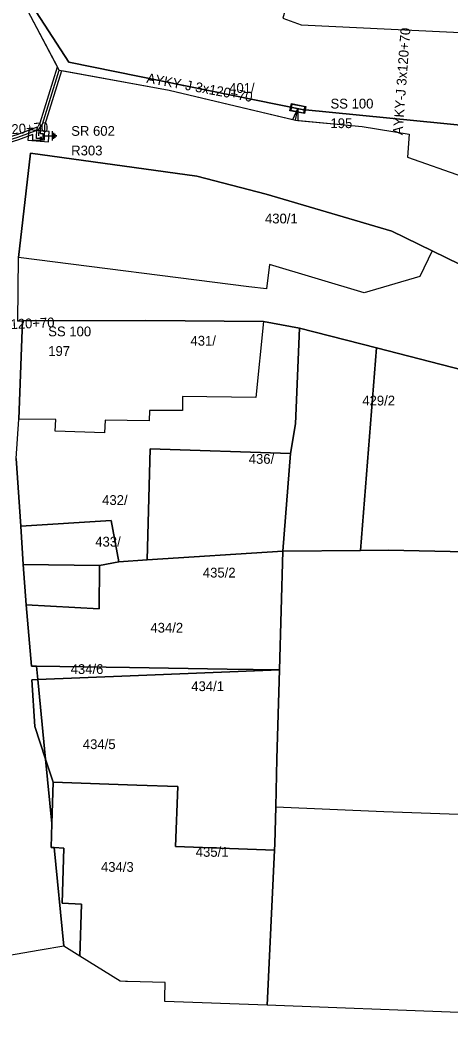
# Model space of a CAD drawing. Extents: x -793400 to -756198, y -1074141 to -1042963.
# Drawn here: x -783578.1 to -783545.2, y -1065386.8 to -1065310.2 of the extents above; entities that cross this region are included whole.
import ezdxf

# ---------------------------------------------------------------- set-up
doc = ezdxf.new("R2010")
doc.units = 0
for name, color, linetype in [('Parcela', 7, 'Continuous'), ('Popiskový text - Parcela', 7, 'Continuous'), ('Popiskový text - Přípojková skříň nn - SJZ', 7, 'Continuous'), ('Popiskový text - Přípojková skříň nn - Typ', 7, 'Continuous'), ('Popiskový text - Rozpojovací skříň nn - SJZ', 7, 'Continuous'), ('Popiskový text - Rozpojovací skříň nn - Typ', 7, 'Continuous'), ('Popiskový text - Vedení nn kabelové', 7, 'Continuous'), ('Skříň', 7, 'Continuous'), ('Spojnice nn', 7, 'Continuous'), ('Stavební objekt', 7, 'Continuous'), ('Uzemnění', 7, 'Continuous'), ('Vedení nn kabelové', 7, 'Continuous')]:
    doc.layers.add(name, color=color, linetype=linetype)

msp = doc.modelspace()

# ---------------------------------------------------------------- linework, layer by layer
at = {"layer": 'Parcela'}
for points in [[(-783571.78, -1065303.16), (-783560.13, -1065304.49), (-783552.66, -1065304.27), (-783552.7, -1065303.7), (-783552.39, -1065303.67), (-783546.16, -1065304.2), (-783541.16, -1065304.39), (-783541.22, -1065311.31), (-783541.24, -1065311.65), (-783541.28, -1065318.54), (-783556.53, -1065317.04), (-783574.41, -1065313.42), (-783576.91, -1065309.57), (-783575.57, -1065302.34)], [(-783542.31, -1065329.92), (-783544.32, -1065335.6), (-783540.78, -1065337.05), (-783540.91, -1065337.84), (-783550.83, -1065335.3), (-783556.72, -1065333.79), (-783559.49, -1065333.28), (-783568.5, -1065333.19), (-783577.94, -1065333.23), (-783578.31, -1065333.24), (-783578.26, -1065328.37), (-783577.34, -1065320.39), (-783564.59, -1065322.15), (-783559.27, -1065323.52), (-783549.65, -1065326.37), (-783546.57, -1065327.87)], [(-783557.03, -1065341.12), (-783557.41, -1065343.37), (-783568.18, -1065343.03), (-783568.41, -1065351.53), (-783570.58, -1065351.67), (-783571.15, -1065348.5), (-783578.09, -1065348.94), (-783578.44, -1065343.77), (-783578.22, -1065340.76), (-783577.94, -1065333.23), (-783568.5, -1065333.19), (-783559.49, -1065333.28), (-783556.72, -1065333.79)], [(-783552.06, -1065350.81), (-783558.01, -1065350.85), (-783557.41, -1065343.37), (-783557.03, -1065341.12), (-783556.72, -1065333.79), (-783550.83, -1065335.3)], [(-783550.83, -1065335.3), (-783540.91, -1065337.84), (-783540.78, -1065337.05), (-783540.39, -1065337.21), (-783541.86, -1065341.83), (-783541, -1065350.97), (-783541.61, -1065350.96), (-783549.93, -1065350.79), (-783552.06, -1065350.81)], [(-783558.01, -1065350.85), (-783568.41, -1065351.53), (-783568.18, -1065343.03), (-783557.41, -1065343.37)], [(-783570.58, -1065351.67), (-783572.04, -1065351.95), (-783577.89, -1065351.89), (-783578.09, -1065348.94), (-783571.15, -1065348.5)], [(-783530.42, -1065371.49), (-783529.82, -1065386.75), (-783559.2, -1065385.61), (-783558.64, -1065373.74), (-783558.62, -1065373.27), (-783558.55, -1065370.42), (-783558.46, -1065366.76), (-783558.27, -1065359.95), (-783558.01, -1065350.85), (-783552.06, -1065350.81), (-783549.93, -1065350.79), (-783541.61, -1065350.96), (-783541, -1065350.97), (-783538.44, -1065351.03), (-783536.05, -1065351.08), (-783531.74, -1065351.18), (-783531.27, -1065359.36), (-783531.27, -1065359.96), (-783531.26, -1065361.25), (-783531.24, -1065365.05), (-783530.77, -1065368.99)], [(-783558.01, -1065350.85), (-783558.27, -1065359.95), (-783562.28, -1065359.89), (-783569.75, -1065359.77), (-783576.87, -1065359.66), (-783577.26, -1065359.65), (-783577.66, -1065354.96), (-783572.07, -1065355.28), (-783572.04, -1065351.95), (-783570.58, -1065351.67), (-783568.41, -1065351.53)], [(-783572.04, -1065351.95), (-783572.07, -1065355.28), (-783577.66, -1065354.96), (-783577.89, -1065351.89)], [(-783569.71, -1065360.4), (-783576.77, -1065360.68), (-783576.87, -1065359.66), (-783569.75, -1065359.77), (-783562.28, -1065359.89), (-783558.27, -1065359.95)], [(-783558.62, -1065373.27), (-783558.64, -1065373.74), (-783566.22, -1065373.48), (-783566.06, -1065368.88), (-783569.18, -1065368.77), (-783575.6, -1065368.55), (-783576.18, -1065366.77), (-783576.77, -1065360.68), (-783569.71, -1065360.4), (-783558.27, -1065359.95), (-783558.46, -1065366.76), (-783558.55, -1065370.42)], [(-783576.77, -1065360.68), (-783576.18, -1065366.77), (-783577, -1065364.27), (-783577.23, -1065360.7)], [(-783575.6, -1065368.55), (-783575.7, -1065371.71), (-783576.18, -1065366.77)], [(-783558.64, -1065373.74), (-783559.2, -1065385.61), (-783567.05, -1065385.34), (-783567.05, -1065385.03), (-783567.02, -1065383.89), (-783569.9, -1065383.8), (-783570.07, -1065383.8), (-783570.46, -1065383.78), (-783573.56, -1065381.86), (-783573.42, -1065377.87), (-783574.91, -1065377.81), (-783574.79, -1065373.59), (-783575.52, -1065373.55), (-783575.76, -1065373.54), (-783575.7, -1065371.71), (-783575.6, -1065368.55), (-783569.18, -1065368.77), (-783566.06, -1065368.88), (-783566.22, -1065373.48)], [(-783573.42, -1065377.87), (-783573.56, -1065381.86), (-783574.79, -1065381.1), (-783575.52, -1065373.55), (-783574.79, -1065373.59), (-783574.91, -1065377.81)]]:
    msp.add_lwpolyline(points, close=True, dxfattribs=at)
for points in [[(-783576.91, -1065309.57), (-783574.41, -1065313.42), (-783556.53, -1065317.04), (-783541.28, -1065318.54)], [(-783542.31, -1065329.92), (-783546.57, -1065327.87), (-783549.65, -1065326.37), (-783559.27, -1065323.52), (-783564.59, -1065322.15), (-783577.34, -1065320.39), (-783578.26, -1065328.37)], [(-783578.31, -1065333.24), (-783577.94, -1065333.23), (-783578.22, -1065340.76)], [(-783578.44, -1065343.77), (-783578.09, -1065348.94), (-783577.89, -1065351.89), (-783577.66, -1065354.96), (-783577.26, -1065359.65), (-783576.87, -1065359.66), (-783576.77, -1065360.68), (-783577.23, -1065360.7), (-783577, -1065364.27), (-783576.18, -1065366.77), (-783575.7, -1065371.71), (-783575.76, -1065373.54), (-783575.52, -1065373.55), (-783574.79, -1065381.1), (-783576.6, -1065381.41), (-783581.05, -1065382.16)]]:
    msp.add_lwpolyline(points, dxfattribs=at)
at = {"layer": 'Skříň'}
for points in [[(-783557.347, -1065316.585), (-783556.244, -1065316.803), (-783556.353, -1065317.355), (-783557.456, -1065317.137)], [(-783556.31, -1065316.848), (-783557.303, -1065316.651), (-783557.39, -1065317.093), (-783556.397, -1065317.289)], [(-783575.904, -1065318.729), (-783577.474, -1065318.606), (-783577.536, -1065319.391), (-783575.966, -1065319.514)]]:
    msp.add_lwpolyline(points, close=True, dxfattribs=at)
at = {"layer": 'Spojnice nn'}
for p, q in [((-783557.04, -1065317.86), (-783556.85, -1065316.97)), ((-783576.69, -1065318.57), (-783576.72, -1065319.06))]:
    msp.add_line(p, q, dxfattribs=at)
for points in [[(-783575.13, -1065314.03), (-783577.55, -1065309.49), (-783575.86, -1065301.58), (-783572.18, -1065301.9), (-783571.88, -1065294.47)], [(-783576.69, -1065318.57), (-783576.41, -1065318.16), (-783575.13, -1065314.03)], [(-783575.13, -1065314.03), (-783566.7, -1065315.57), (-783557.04, -1065317.86)], [(-783557.04, -1065317.86), (-783551.91, -1065318.35), (-783548.32, -1065318.93), (-783548.45, -1065320.69), (-783544.23, -1065322.17), (-783541.68, -1065322.57)], [(-783588.03, -1065320.22), (-783586.62, -1065320.12), (-783580.13, -1065319.72), (-783578.32, -1065319.17), (-783576.69, -1065318.57)]]:
    msp.add_lwpolyline(points, dxfattribs=at)
at = {"layer": 'Stavební objekt'}
for points in [[(-783541.24, -1065311.65), (-783541.28, -1065318.54), (-783556.53, -1065317.04), (-783574.41, -1065313.42), (-783576.91, -1065309.57), (-783575.57, -1065302.34), (-783571.78, -1065303.16), (-783561.7, -1065305.22), (-783556.94, -1065306.21), (-783557.99, -1065310.05), (-783556.6, -1065310.57), (-783541.22, -1065311.31)], [(-783546.57, -1065327.87), (-783547.51, -1065329.82), (-783551.77, -1065331.07), (-783559.02, -1065328.91), (-783559.26, -1065330.78), (-783560.62, -1065330.61), (-783578.26, -1065328.37), (-783577.34, -1065320.39), (-783564.59, -1065322.15), (-783559.27, -1065323.52), (-783549.65, -1065326.37)], [(-783559.49, -1065333.28), (-783560.08, -1065339.1), (-783565.7, -1065339.01), (-783565.7, -1065340.1), (-783568.23, -1065340.1), (-783568.24, -1065340.87), (-783571.62, -1065340.84), (-783571.66, -1065341.81), (-783575.44, -1065341.66), (-783575.4, -1065340.77), (-783578.22, -1065340.76), (-783577.94, -1065333.23), (-783568.5, -1065333.19)], [(-783570.58, -1065351.67), (-783572.04, -1065351.95), (-783577.89, -1065351.89), (-783578.09, -1065348.94), (-783571.15, -1065348.5)], [(-783558.01, -1065350.85), (-783558.27, -1065359.95), (-783562.28, -1065359.89), (-783569.75, -1065359.77), (-783576.87, -1065359.66), (-783577.26, -1065359.65), (-783577.66, -1065354.96), (-783572.07, -1065355.28), (-783572.04, -1065351.95), (-783570.58, -1065351.67), (-783568.41, -1065351.53)], [(-783572.04, -1065351.95), (-783572.07, -1065355.28), (-783577.66, -1065354.96), (-783577.89, -1065351.89)], [(-783558.64, -1065373.74), (-783559.2, -1065385.61), (-783567.05, -1065385.34), (-783567.05, -1065385.03), (-783567.02, -1065383.89), (-783569.9, -1065383.8), (-783570.07, -1065383.8), (-783570.46, -1065383.78), (-783573.56, -1065381.86), (-783573.42, -1065377.87), (-783574.91, -1065377.81), (-783574.79, -1065373.59), (-783575.52, -1065373.55), (-783575.76, -1065373.54), (-783575.7, -1065371.71), (-783575.6, -1065368.55), (-783569.18, -1065368.77), (-783566.06, -1065368.88), (-783566.22, -1065373.48)], [(-783530.42, -1065371.49), (-783529.82, -1065386.75), (-783559.2, -1065385.61), (-783558.64, -1065373.74), (-783558.62, -1065373.27), (-783558.55, -1065370.42), (-783550.26, -1065370.78), (-783535.28, -1065371.32)]]:
    msp.add_lwpolyline(points, close=True, dxfattribs=at)
at = {"layer": 'Uzemnění'}
for p, q in [((-783576.326, -1065319.06), (-783575.641, -1065319.06)), ((-783575.641, -1065319.406), (-783575.641, -1065318.715)), ((-783575.549, -1065319.281), (-783575.549, -1065318.84)), ((-783575.45, -1065319.204), (-783575.45, -1065318.919)), ((-783575.343, -1065319.112), (-783575.343, -1065319.012))]:
    msp.add_line(p, q, dxfattribs=at)
at = {"layer": 'Vedení nn kabelové'}
for points in [[(-783576.562, -1065319.15), (-783576.562, -1065319.302), (-783576.365, -1065319.302), (-783576.365, -1065318.912), (-783576.561, -1065318.912), (-783576.54, -1065318.579), (-783576.592, -1065318.072), (-783575.262, -1065313.782), (-783577.55, -1065309.49), (-783575.86, -1065301.58), (-783572.18, -1065301.9), (-783571.888, -1065294.666), (-783571.11, -1065294.58)], [(-783576.588, -1065319.15), (-783576.588, -1065319.356), (-783576.271, -1065319.356), (-783576.271, -1065319.087), (-783576.241, -1065318.597), (-783576.228, -1065318.248), (-783574.932, -1065314.066), (-783566.7, -1065315.57), (-783557.235, -1065317.814), (-783556.85, -1065316.97)], [(-783576.537, -1065319.15), (-783576.537, -1065319.276), (-783576.87, -1065319.276), (-783576.87, -1065319.051), (-783576.83, -1065318.408), (-783578.384, -1065318.98), (-783580.166, -1065319.522), (-783586.633, -1065319.92), (-783588.033, -1065320.02), (-783588.087, -1065315.959), (-783588.93, -1065315.78)], [(-783556.85, -1065316.97), (-783556.84, -1065317.879), (-783551.91, -1065318.35), (-783548.32, -1065318.93), (-783548.45, -1065320.69), (-783544.23, -1065322.17), (-783541.644, -1065322.373), (-783540.8, -1065322.73)], [(-783576.513, -1065319.15), (-783576.513, -1065319.427), (-783577.169, -1065319.427), (-783577.169, -1065319.032), (-783577.165, -1065318.958), (-783578.256, -1065319.36), (-783580.094, -1065319.918), (-783588.015, -1065320.406), (-783587.056, -1065332.478), (-783588.886, -1065332.306), (-783589.16, -1065331.48)]]:
    msp.add_lwpolyline(points, dxfattribs=at)

# ---------------------------------------------------------------- texts
at = {"layer": 'Popiskový text - Parcela'}
for s, p in [('401/', (-783562.115, -1065315.775)), ('430/1', (-783559.371, -1065325.767)), ('431/', (-783565.08, -1065335.124)), ('429/2', (-783551.913, -1065339.703)), ('436/', (-783560.615, -1065344.17)), ('432/', (-783571.847, -1065347.32)), ('433/', (-783572.375, -1065350.509)), ('435/2', (-783564.132, -1065352.877)), ('434/2', (-783568.15, -1065357.096)), ('434/6', (-783574.262, -1065360.262)), ('434/1', (-783565.02, -1065361.571)), ('434/5', (-783573.327, -1065366.01)), ('435/1', (-783564.674, -1065374.255)), ('434/3', (-783571.939, -1065375.406))]:
    msp.add_text(s, height=0.75, dxfattribs=at).set_placement(p)
at = {"layer": 'Popiskový text - Přípojková skříň nn - SJZ'}
for s, p in [('195', (-783554.35, -1065318.47)), ('197', (-783575.98, -1065335.91))]:
    msp.add_text(s, height=0.75, dxfattribs=at).set_placement(p)
at = {"layer": 'Popiskový text - Přípojková skříň nn - Typ'}
for p in [(-783554.35, -1065316.97), (-783575.98, -1065334.41)]:
    msp.add_text('SS 100', height=0.75, dxfattribs=at).set_placement(p)
at = {"layer": 'Popiskový text - Rozpojovací skříň nn - SJZ'}
msp.add_text('R303', height=0.75, dxfattribs=at).set_placement((-783574.22, -1065320.56))
at = {"layer": 'Popiskový text - Rozpojovací skříň nn - Typ'}
msp.add_text('SR 602', height=0.75, dxfattribs=at).set_placement((-783574.22, -1065319.06))
at = {"layer": 'Popiskový text - Vedení nn kabelové'}
for rotation, p in [(85.77178, (-783548.828, -1065319.018)), (349.61885, (-783568.486, -1065314.99)), (3.55234, (-783584.169, -1065319.268)), (2.52101, (-783583.702, -1065334.073))]:
    msp.add_text('AYKY-J 3x120+70', height=0.75, rotation=rotation, dxfattribs=at).set_placement(p)

doc.saveas('drawing.dxf')
